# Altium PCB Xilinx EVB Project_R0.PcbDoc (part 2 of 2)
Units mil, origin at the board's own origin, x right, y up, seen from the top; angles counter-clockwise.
Board outline 8120 x 5778 mil, 6 copper layers (Top Layer, Mid-Layer 1, Mid-Layer 2, Mid-Layer 3, Mid-Layer 4, Bottom Layer); 283 components, 125 nets, 1037 pads, 1290 vias.
Unrouted connection lines stored in the file: 1.
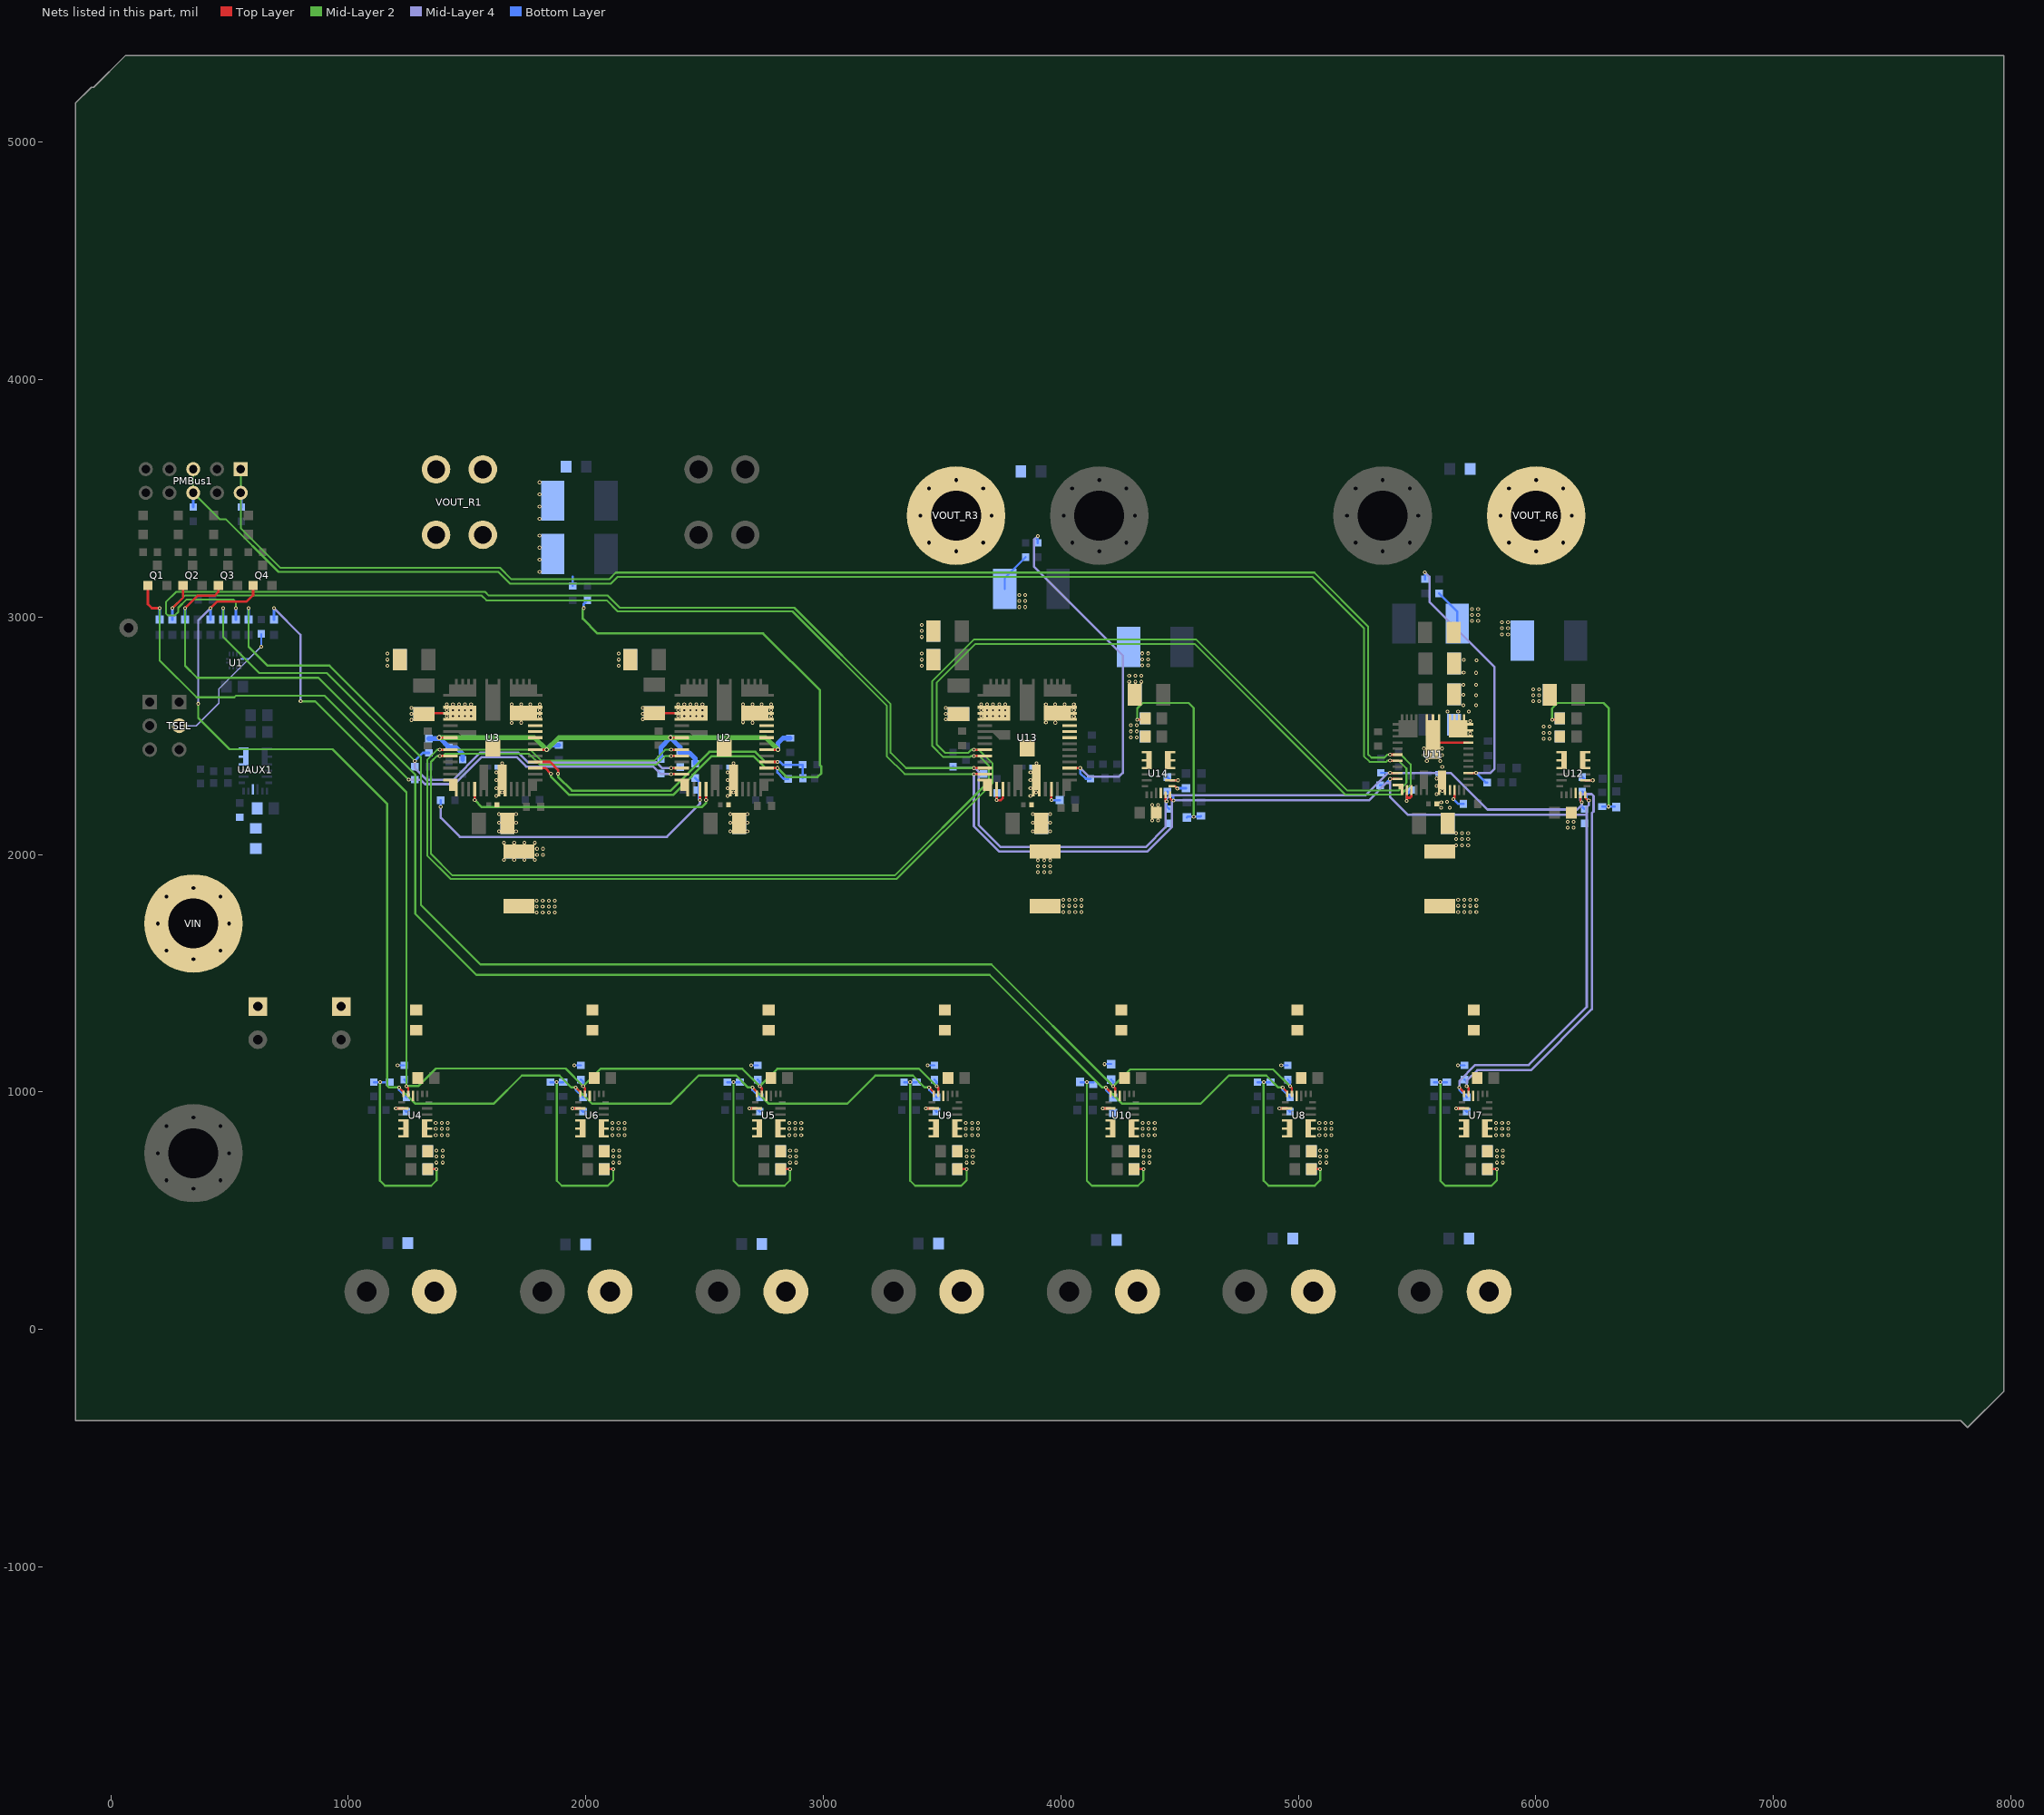
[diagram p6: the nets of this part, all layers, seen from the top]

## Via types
v1: diameter 15.75, hole 7.87, Top Layer to Bottom Layer, tented both sides, 1280 vias
v2: diameter 19.68, hole 11.81, Top Layer to Bottom Layer, tented both sides, 10 vias

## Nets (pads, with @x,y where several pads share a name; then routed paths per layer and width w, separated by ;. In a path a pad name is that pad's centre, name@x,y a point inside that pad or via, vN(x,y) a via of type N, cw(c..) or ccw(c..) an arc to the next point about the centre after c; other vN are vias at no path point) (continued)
NetR45_1: R45.1 U4.2 | length 82.7
  Top Layer w10: v1(1200.07,930.43) U4.2@1232.79,930.43
  Bottom Layer w10: v1(1200.07,930.43) 1231.07,930.43 R45.1@1244.5,917
NetR50_1: R50.1 U5.2 | length 82.7
  Top Layer w10: v1(2688.23,930.43) U5.2@2720.95,930.43
  Bottom Layer w10: v1(2688.23,930.43) 2719.23,930.43 R50.1@2732.67,917
NetR55_2: R55.2 U6.2 | length 82.7
  Top Layer w10: v1(1944.15,930.43) U6.2@1976.87,930.43
  Bottom Layer w10: v1(1944.15,930.43) 1975.15,930.43 R55.2@1988.58,917
NetR60_2: R60.2 U7.2 | length 82.7
  Top Layer w10: v1(5664.57,930.43) U7.2@5697.29,930.43
  Bottom Layer w10: v1(5664.57,930.43) 5695.57,930.43 R60.2@5709,917
NetR65_1: R65.1 U8.2 | length 82.7
  Top Layer w10: v1(4920.48,930.43) U8.2@4953.2,930.43
  Bottom Layer w10: v1(4920.48,930.43) 4951.48,930.43 R65.1@4964.92,917
NetR70_1: R70.1 U9.2 | length 82.7
  Top Layer w10: v1(3432.32,930.43) U9.2@3465.04,930.43
  Bottom Layer w10: v1(3432.32,930.43) 3463.32,930.43 R70.1@3476.75,917
NetR75_2: R75.2 U10.2 | length 82.7
  Top Layer w10: v1(4176.4,930.43) U10.2@4209.12,930.43
  Bottom Layer w10: v1(4176.4,930.43) 4207.4,930.43 R75.2@4220.83,917
NetR84_1: R84.1 R85.2 U11.3 | length 1159.2
  Top Layer w10: U11.3@5715.62,2343.63 v1(5747.6,2343.63)
  Mid-Layer 4 w10: v1(5533,3188) 5552,3169 5552,3063.06 5826,2789.06 5826,2361 5808.63,2343.63 v1(5747.6,2343.63)
  Bottom Layer w10: R85.2@5533,3159 v1(5533,3188) ; v1(5747.6,2343.63) 5788.23,2303 R84.1@5795,2303
NetR86_2: R86.2 U11.43 | length 90.9
  Top Layer w10: v1(5653,2233) 5657.55,2237.55 U11.43@5657.55,2271.78
  Bottom Layer w10: v1(5653,2233) 5673,2213 R86.2@5695,2213
NetR89_2: R89.2 U12.2 | length 82.7
  Top Layer w10: U12.2@6207.21,2312.4 v1(6239.93,2312.4)
  Bottom Layer w10: R89.2@6195.5,2325.83 6208.93,2312.4 v1(6239.93,2312.4)
NetR98_2: R98.2 R99.2 U13.3 | length 1509.4
  Top Layer w10: U13.3@4036.15,2364.05 v1(4081.82,2364.05)
  Mid-Layer 4 w10: v1(3903,3341) 3887,3325 3887,3212 4261,2838 4261,2344 4244,2327 4118.87,2327 v1(4081.82,2364.05)
  Bottom Layer w10: R99.2@3903,3312 v1(3903,3341) ; v1(4081.82,2364.05) 4081.82,2342.18 4105,2319 R98.2@4125,2319
NetR100_1: R100.1 U13.48 | length 80.1
  Top Layer w10: v1(3960.36,2228.81) U13.48@3960.36,2274.48
  Bottom Layer w10: v1(3960.36,2228.81) R100.1@3994.81,2228.81
NetR103_2: R103.2 U14.2 | length 82.7
  Top Layer w10: U14.2@4460.21,2312.4 v1(4492.93,2312.4)
  Bottom Layer w10: R103.2@4448.5,2325.83 4461.93,2312.4 v1(4492.93,2312.4)
NetR104_2: R104.2 U14.1 | length 63.1
  Top Layer w9: U14.1@4468.09,2286.81 4481.52,2286.81 v1(4490.5,2277.83)
  Bottom Layer w10: v1(4490.5,2277.83) 4491.67,2279 R104.2@4527,2279
NetU2_8: U2.8 U2.9 U2.10 U2.11 U2.12 U2.13 U2.51
  other v1: 2702,2555 2662,2557 2780,2581 2780,2607 2662,2633 2701.33,2633 2740.67,2633 2780,2633
NetU2_38: U2.38 U2.39
NetU2_42: U2.42 U3.42 | length 1097.4
  Top Layer w10: v1(1532.23,2228.81) U3.42@1532.23,2274.48 ; v1(2506.23,2228.81) U2.42@2506.23,2274.48
  Mid-Layer 2 w10: v1(1532.23,2228.81) 1562.04,2199 2489,2199 2506.23,2216.23 v1(2506.23,2228.81)
NetU3_8: U3.8 U3.9 U3.10 U3.11 U3.12 U3.13 U3.51
  other v1: 1688,2554 1728,2555 1806,2581 1806,2607 1688,2633 1727.33,2633 1766.67,2633 1806,2633
NetU3_38: U3.38 U3.39
NetU4_4: U4.4 U4.5 U4.6
NetU5_4: U5.4 U5.5 U5.6
NetU6_4: U6.4 U6.5 U6.6
NetU7_4: U7.4 U7.5 U7.6
NetU8_4: U8.4 U8.5 U8.6
NetU9_4: U9.4 U9.5 U9.6
NetU10_4: U10.4 U10.5 U10.6
NetU11_8: U11.8 U11.16 U11.17 U11.18 | length 153.5
  Top Layer w10: U11.16@5567,2483.39 5578.81,2471.58 U11.8@5715.62,2471.58
  other v1: 5541,2394 5597,2394 5529,2418 5605,2418 5529,2446 5605,2446
NetU11_33: U11.33 U11.34 U11.42
NetU12_4: U12.4 U12.5 U12.6
NetU13_8: U13.8 U13.9 U13.10 U13.11 U13.12 U13.13 U13.51
  other v1: 3977,2555 3937,2556 4055,2581 4055,2607 3937,2633 3976.33,2633 4015.67,2633 4055,2633
NetU13_38: U13.38 U13.39
NetU14_4: U14.4 U14.5 U14.6
NetUAUX1_4: UAUX1.4 UAUX1.5 UAUX1.6
SCL: PMBus1.1 PMBus1.2 R32.2 U2.33 U3.33 U11.28 U13.33 | length 13292.5
  Top Layer w10: v1(1385.18,2440.82) U3.33@1430.85,2440.82 ; v1(2359.18,2440.82) U2.33@2404.85,2440.82 ; v1(3634.18,2440.82) U13.33@3679.85,2440.82 ; v1(5386.4,2420.4) U11.28@5418.38,2420.4
  Mid-Layer 2 w8: PMBus1.1@547,3623 PMBus1.2@547,3523 547,3374.37 713.43,3207.94 1638.43,3207.94 1687.43,3158.94 2098.57,3158.94 2126.57,3186.94 5067.43,3186.94 5294,2960.37 5294,2421.37 5307.43,2407.94 5362.58,2407.94 5375.04,2420.4 v1(5386.4,2420.4) 5431.6,2420.4 5472.94,2379.06 5472.94,2293.94 5431.06,2252.06 5197.94,2252.06 4563,2887 3641,2887 3477,2723 3477,2464 3513.06,2427.94 3609.94,2427.94 3622.82,2440.82 v1(3634.18,2440.82) 3655.18,2440.82 3713,2383 3713,2301 3309,1897 1430.75,1897 1332,1995.75 1332,2399 1373.82,2440.82 v1(1385.18,2440.82) 1766.81,2440.82 1812.73,2394.9 2287.9,2394.9 2333.82,2440.82 2337.19,2440.82 2337.87,2441.5 2351.13,2441.5 2351.81,2440.82 v1(2359.18,2440.82)
  Bottom Layer w8: PMBus1.2@547,3523 PMBus1.2@550,3520
  Bottom Layer w10: R32.2@550,3463 PMBus1.2@550,3520
SDA: PMBus1.5 PMBus1.6 R33.1 U2.34 U3.34 U11.29 U13.34 | length 13278.9
  Top Layer w10: v1(1385.18,2415.23) U3.34@1430.85,2415.23 ; v1(2359.18,2415.23) U2.34@2404.85,2415.23 ; v1(3634.18,2415.23) U13.34@3679.85,2415.23 ; v1(5386.4,2394.81) U11.29@5418.38,2394.81
  Mid-Layer 2 w8: PMBus1.5@347,3623 PMBus1.6@347,3523 458,3412 484,3412 706,3190 1631,3190 1680,3141 2106,3141 2134,3169 5060,3169 5276.06,2952.94 5276.06,2413.94 5300,2390 5370.01,2390 5374.82,2394.81 v1(5386.4,2394.81) 5422.19,2394.81 5455,2362 5455,2301.37 5423.63,2270 5205.37,2270 4570.43,2904.94 3633.57,2904.94 3459.06,2730.43 3459.06,2456.57 3505.63,2410 3617.37,2410 3622.6,2415.23 v1(3634.18,2415.23) 3655.77,2415.23 3697,2374 3697,2307.63 3302.37,1913 1437.37,1913 1348,2002.37 1348,2389.63 1373.6,2415.23 v1(1385.18,2415.23) 1398.41,2415.23 1408,2424.82 1760.18,2424.82 1806.1,2378.9 2297.9,2378.9 2334.23,2415.23 v1(2359.18,2415.23)
  Bottom Layer w10: R33.1@347,3463 PMBus1.6@347,3523
SEQ_EN1: R17.2 R29.2 R36.2 R39.1 U2.36 | length 2577.4
  Top Layer w10: v1(2359.18,2364.05) U2.36@2404.85,2364.05
  Mid-Layer 2 w8: v1(473.22,3037) 473.22,2915.78 625,2764 910,2764 v1(1280,2394)
  Mid-Layer 4 w10: v1(1280,2394) 1280,2365 1331,2314 1440.54,2314 1554.54,2428 1716.46,2428 1756.46,2388 2297,2388 2320.95,2364.05 v1(2359.18,2364.05)
  Bottom Layer w10: R17.2@473.22,2989 v1(473.22,3037) ; R39.1@1280,2370 v1(1280,2394) 1314,2428 R36.2@1339,2428 ; v1(2359.18,2364.05) 2393.05,2364.05 R29.2@2397,2368
SEQ_EN2: R16.2 R57.1 R81.1 R87.1 R95.1 R101.1 U7.17 U11.31 U12.17 U13.36 U14.17 | length 9496.6
  Top Layer w9: U14.17@4440.53,2251.37 4440.53,2227.47 v1(4445,2223) ; v1(5709,1024) 5716.97,1016.03 U7.17@5716.97,991.46 ; U12.17@6187.53,2251.37 6187.53,2225.47 v1(6193,2220)
  Top Layer w10: v1(3634.18,2364.05) U13.36@3679.85,2364.05 ; v1(5386.4,2343.63) U11.31@5418.38,2343.63
  Mid-Layer 2 w8: v1(526.67,3037) 526.67,3062.33 515,3074 319.07,3074 284,3038.93 284,3021 270,3007 240,3007 232,3015 232,3063 275,3106 1576,3106 1592,3090 2093,3090 2144,3039 2877.63,3039 3283,2633.63 3283,2429 3347.95,2364.05 v1(3634.18,2364.05)
  Mid-Layer 4 w10: v1(3634.18,2364.05) 3638.11,2364.05 3655.06,2347.1 3655.06,2328.76 3654,2327.7 3654,2124.46 3747.46,2031 4357.54,2031 4440.53,2113.98 4440.53,2218.53 v1(4445,2223) 4445,2234.85 4458.85,2248.7 5282.7,2248.7 5377.63,2343.63 v1(5386.4,2343.63) 5641.37,2343.63 5796,2189 6174,2189 6195,2210 6195,2220.36 6187.53,2227.83 6187.53,2244.53 6197,2254 6235,2254 6243,2246 6243,2181 6236,2174 6236,1348.59 5978.91,1091.5 5753.91,1091.5 5709,1046.59 v1(5709,1024)
  Bottom Layer w9: v1(4445,2223) 4445,2203.33 R101.1@4457.5,2190.83 ; R81.1@5347,2344 5386.03,2344 v1(5386.4,2343.63) ; R57.1@5700,1052 5709,1043 v1(5709,1024) ; v1(6193,2220) 6193,2202.33 R87.1@6204.5,2190.83
  Bottom Layer w10: R16.2@526.67,2989 v1(526.67,3037) ; R95.1@3546,2370 3551.95,2364.05 v1(3634.18,2364.05)
SEQ_EN3: R15.2 R62.2 R73.1 U8.17 U10.17 | length 5920.5
  Top Layer w9: v1(4220.83,1024) 4228.81,1016.03 U10.17@4228.81,991.46 ; v1(4964.92,1024) 4972.89,1016.03 U8.17@4972.89,991.46
  Mid-Layer 2 w9: v1(580.11,3037) 580.11,2874.89 660,2795 921,2795 1306,2410 1306,1787 1556,1537 3707.83,1537 v1(4220.83,1024) 4291.83,1095 4893.92,1095 v1(4964.92,1024)
  Bottom Layer w9: R73.1@4211.83,1052 4220.83,1043 v1(4220.83,1024) ; R62.2@4955.92,1052 4964.92,1043 v1(4964.92,1024)
  Bottom Layer w10: R15.2@580.11,2989 v1(580.11,3037)
SEQ_EN4: R9.2 R42.2 R47.2 R52.1 R67.2 U4.17 U5.17 U6.17 U9.17 | length 5014.7
  Top Layer w9: v1(1244.5,1024) 1252.47,1016.03 U4.17@1252.47,991.46 ; v1(1988.58,1024) 1996.56,1016.03 U6.17@1996.56,991.46 ; v1(2732.67,1024) 2740.64,1016.03 U5.17@2740.64,991.46 ; v1(3476.75,1024) 3484.72,1016.03 U9.17@3484.72,991.46
  Mid-Layer 2 w9: v1(799,2645) 861,2645 1244.5,2261.5 v1(1244.5,1024) ; v1@1244.92,1024.42 1294.42,1024.42 1368.42,1098.42 1915,1098.42 v1@1989,1024.42 ; v1(1988.58,1024) v1@1989,1024.42 ; v1(3476.75,1024) 3402.75,1098 2806.67,1098 v1(2732.67,1024) 2658.67,1098 2062.58,1098 v1@1989,1024.42
  Mid-Layer 4 w9: v1(687,3037) 799,2925 v1(799,2645)
  Bottom Layer w9: R42.2@1235.5,1052 1244.5,1043 v1(1244.5,1024) ; R52.1@1979.58,1052 1988.58,1043 v1(1988.58,1024) ; R47.2@2723.67,1052 2732.67,1043 v1(2732.67,1024) ; R67.2@3467.75,1052 3476.75,1043 v1(3476.75,1024)
  Bottom Layer w10: R9.2@687,2989 v1(687,3037)
SEQ_PG1: Q1.1 R10.1 R31.2 R38.1 U2.37 | length 2970.8
  Top Layer w10: Q1.1@156,3133 156,3054 173,3037 v1(206,3037) ; v1(2359.18,2338.46) U2.37@2404.85,2338.46
  Mid-Layer 2 w8: v1(206,3037) 206,2817 361,2662 520,2662 526,2668 901,2668 v1(1254,2315)
  Mid-Layer 4 w10: v1(1254,2315) 1304.54,2315 1323.54,2296 1448,2296 1562,2410 1709,2410 1749,2370 2284,2370 2315.54,2338.46 v1(2359.18,2338.46)
  Bottom Layer w10: R10.1@206,2989 v1(206,3037) ; v1(1254,2315) R38.1@1280,2315 ; R31.2@2316,2341 2318.54,2338.46 v1(2359.18,2338.46)
SEQ_PG2: Q2.1 R11.1 R60.1 R83.1 R89.1 R97.2 R103.1 U7.18 U11.32 U12.18 U13.37 U14.18 | length 9111.9
  Top Layer w9: v1(259.44,3037) 304,3081.56 Q2.1@304,3133 ; U14.18@4460.21,2251.37 4460.9,2250.69 4460.9,2234.43 v1@4467.5,2227.83 ; v1(5678,1019) 5697.29,999.71 U7.18@5697.29,991.46 ; U12.18@6207.21,2251.37 6207.21,2239.79 6220,2227 v1(6223,2227)
  Top Layer w10: v1(3634.18,2338.46) U13.37@3679.85,2338.46 ; v1(5386.4,2318.04) U11.32@5418.38,2318.04
  Mid-Layer 2 w8: v1(259.44,3037) 312.44,3090 1562,3090 1582,3070 2088,3070 2134,3024 2870,3024 3267,2627 3267,2414 3342.54,2338.46 v1(3634.18,2338.46)
  Mid-Layer 4 w10: v1(3634.18,2338.46) 3634.18,2118.82 3740,2013 4365,2013 4467.5,2115.5 4467.5,2221.33 v1(4474,2227.83) 5296.83,2227.83 5370,2301 5385,2301 ; v1(5386.4,2318.04) 5386.4,2242.6 5462,2167 6214.5,2167 ; v1(5678,1019) 5678,1046 5745,1113 5970,1113 6214.5,1357.5 6214.5,2167 ; v1(6223,2227) 6223,2209 6214.5,2200.5 6214.5,2167
  Bottom Layer w9: R103.1@4448.5,2265.83 4474,2240.33 v1(4474,2227.83) ; v1(5678,1019) 5678,1008 R60.1@5709,977 ; R89.1@6195.5,2265.83 6214.5,2246.83 6214.5,2235.5 v1(6223,2227)
  Bottom Layer w10: R11.1@259.44,2989 v1(259.44,3037) ; v1(3634.18,2338.46) 3674.46,2338.46 R97.2@3675,2339 ; R83.1@5344,2291 5359.36,2291 v1(5386.4,2318.04)
SEQ_PG3: Q3.1 R12.1 R65.2 R75.1 U8.18 U10.18 | length 6465.1
  Top Layer w9: v1(4189.83,1019) 4209.12,999.71 U10.18@4209.12,991.46 ; v1(4933.92,1019) 4953.2,999.71 U8.18@4953.2,991.46
  Top Layer w10: v1(312.89,3037) 364.89,3089 437,3089 453,3105 Q3.1@453,3132
  Mid-Layer 2 w9: v1(312.89,3037) 312.89,2794.11 363,2744 874,2744 1282,2336 1282,1750 1539,1493 3700,1493 4174,1019 v1(4189.83,1019) 4258.83,950 4588.33,950 4707.33,1069 4865.17,1069 4915.17,1019 v1(4933.92,1019)
  Bottom Layer w9: v1(4189.83,1019) 4189.83,1008 R75.1@4220.83,977 ; v1(4933.92,1019) 4933.92,1008 R65.2@4964.92,977
  Bottom Layer w10: R12.1@312.89,2989 v1(312.89,3037)
SEQ_PG4: Q4.1 R13.1 R45.2 R50.2 R55.1 R70.2 U4.18 U5.18 U6.18 U9.18 | length 5845.7
  Top Layer w9: v1(1213.5,1019) 1232.79,999.71 U4.18@1232.79,991.46 ; v1(1957.58,1019) 1976.87,999.71 U6.18@1976.87,991.46 ; v1(2701.67,1019) 2720.95,999.71 U5.18@2720.95,991.46 ; v1(3445.75,1019) 3465.04,999.71 U9.18@3465.04,991.46
  Top Layer w10: v1(419.78,3037) 447.78,3065 572,3065 599,3092 Q4.1@599,3130
  Mid-Layer 2 w9: v1(368,2635) 368,2575 500,2443 934,2443 1163,2214 1163,1028 1172,1019 v1(1213.5,1019) 1282.5,950 1612,950 1731,1069 1888.83,1069 1938.83,1019 v1(1957.58,1019) 2026.58,950 2356.08,950 2475.08,1069 2632.92,1069 2682.92,1019 v1(2701.67,1019) 2770.67,950 3100.17,950 3219.17,1069 3377,1069 3427,1019 v1(3445.75,1019)
  Mid-Layer 4 w9: v1(368,2635) 368,2985.22 v1(419.78,3037)
  Bottom Layer w9: v1(1213.5,1019) 1213.5,1008 R45.2@1244.5,977 ; v1(1957.58,1019) 1957.58,1008 R55.1@1988.58,977 ; v1(2701.67,1019) 2701.67,1008 R50.2@2732.67,977 ; v1(3445.75,1019) 3445.75,1008 R70.2@3476.75,977
  Bottom Layer w10: R13.1@419.78,2989 v1(419.78,3037)
TAKE1: R22.1 R35.1 R41.2 U2.41 | length 1418.6
  Top Layer w10: v1(2480.64,2228.81) U2.41@2480.64,2274.48
  Mid-Layer 4 w10: v1(1389,2200) 1389,2155 1470,2074 2341,2074 2480.64,2213.64 v1(2480.64,2228.81)
  Bottom Layer w10: v1(1389,2200) R41.2@1389,2228 ; R22.1@2460,2322 2475.92,2306.08 2475.92,2233.53 v1(2480.64,2228.81)
TAKE2: R91.1 U13.40 U13.41 | length 142.3
  Top Layer w10: U13.40@3730.05,2274.48 v1(3730.05,2228.81) 3746.81,2228.81 3755.64,2237.64 U13.41@3755.64,2274.48
  Bottom Layer w10: v1(3730.05,2228.81) 3730.05,2258.05 R91.1@3731,2259
TAKE3: R77.2 U11.35 U11.36 | length 148.8
  Top Layer w10: v1(5456.76,2225.76) 5456.76,2242.24 ; U11.35@5456.76,2271.78 5456.76,2242.24 ; U11.36@5476.45,2271.78 5476.45,2245.45 5470,2239 5460,2239 5456.76,2242.24
  Bottom Layer w10: v1(5456.76,2225.76) 5456.76,2252.76 R77.2@5475,2271
TSEL: R5.1 TSEL.2 U1.11 | length 673.8
  Mid-Layer 4 w6: TSEL.2@288,2542 360,2542 455,2637 455,2697 v1(633.56,2875.56)
  Bottom Layer w6: U1.11@553.51,2823.87 581.87,2823.87 v1(633.56,2875.56) R5.1@633.56,2929
VCC_U1: C18.2 C29.2 R22.2 R29.1 R30.1 R31.1 R36.1 R37.1 U2.6 U2.31 U3.6 U3.31 | length 2310.1
  Top Layer w10: v2(1383,2492) U3.31@1430.85,2492 ; U3.6@1787.15,2440.82 v2(1835,2440.82) ; v2(2357,2492) U2.31@2404.85,2492 ; U2.6@2761.15,2440.82 v2(2809,2440.82)
  Mid-Layer 2 w20: v2(1383,2492) 1783.82,2492 v2(1835,2440.82) 1886.18,2492 v2(2357,2492) 2757.82,2492 v2(2809,2440.82)
  Bottom Layer w20: R36.1@1339,2488 1379,2488 v2(1383,2492) R30.1@1424,2451 1454,2451 1482,2423 R37.1@1482,2399 ; v2(1835,2440.82) 1854.18,2460 C29.2@1886,2460 ; R31.1@2316,2401 2316,2451 v2(2357,2492) 2397,2452 R29.1@2397,2428 2437,2428 2460,2405 R22.2@2460,2382 ; v2(2809,2440.82) 2809,2469 2830,2490 C18.2@2861,2490
VIN: C12.1 C13.1 R1.1 R23.1 R24.1 R43.1 R48.1 R53.1 R58.1 R63.1 R68.1 R72.1 R78.1 R92.1 VIN.1 VIN.2 VIN.3 VIN.4 VIN.5 VIN.6 VIN.7 VIN.8 VIN.9
  other v1: 1793,1755 1818.5,1755 1844,1755 1869.5,1755 4010,1758 4035.5,1758 4061,1758 4086.5,1758 5673,1758 5698.5,1758 5724,1758 5749.5,1758 1793,1780.5 1818.5,1780.5 1844,1780.5 1869.5,1780.5 4010,1783.5 4035.5,1783.5 4061,1783.5 4086.5,1783.5 5673,1783.5 5698.5,1783.5 5724,1783.5 5749.5,1783.5 1793,1806 1818.5,1806 1844,1806 1869.5,1806 4010,1809 4035.5,1809 4061,1809 4086.5,1809 5673,1809 5698.5,1809 5724,1809 5749.5,1809
VIN1: C14.2 C15.2 C16.2 C17.2 C25.2 C26.2 C27.2 C28.2 R23.2 R24.2 U2.45 U2.46 U3.45 U3.46
  other v1: 1655,1977 1698.33,1977 1741.67,1977 1785,1977 1794,1998.5 1819.5,1998.5 1794,2024 1819.5,2024 1655,2049 1698.33,2049 1741.67,2049 1785,2049 1634,2097 1706,2097 2608,2097 2680,2097 1634,2133.5 1706,2133.5 2608,2133.5 2680,2133.5 1634,2170 1706,2170 2608,2170 2680,2170 1623,2246 2597,2246 1647,2262 2621,2262 1623,2279.33 2597,2279.33 1623,2312.67 2597,2312.67 1623,2346 2597,2346 1648,2384 2622,2384
VIN2: C68.2 R72.2 R73.2 U10.16 | length 28
  Bottom Layer w8: v1(4183.83,1117) R73.2@4211.83,1117
VIN3: C102.2 C103.2 C104.2 C105.2 C114.2 R92.2 R101.2 U13.45 U13.46 U14.16
  other v1: 3904,1925 3929.5,1925 3955,1925 3904,1950.5 3929.5,1950.5 3955,1950.5 3904,1976 3929.5,1976 3955,1976 3883,2097 3955,2097 3883,2133.5 3955,2133.5 4385,2144 4409,2144 3883,2170 3955,2170 4385,2209 4409,2209 3872,2246 3896,2262 3872,2279.33 3872,2312.67 3872,2346 3897,2384
VIN4: C44.2 R52.2 R53.2 U6.16 | length 28
  Bottom Layer w8: v1(1951.58,1112) R52.2@1979.58,1112
VIN5: C50.2 R57.2 R58.2 U7.16 | length 28
  Bottom Layer w8: v1(5672,1112) R57.2@5700,1112
VIN6: C76.2 C77.2 C90.2 C120.2 C121.2 R78.2 R87.2 U11.40 U11.41 U12.16
  other v1: 5664,2039 5689.5,2039 5715,2039 5664,2064.5 5689.5,2064.5 5715,2064.5 5664,2090 5689.5,2090 5715,2090 6134,2112.5 6159.5,2112.5 6134,2138 6159.5,2138 5601,2197 5637,2197 5602,2220 5626,2221 5582,2254 5606,2267 5582,2289 5582,2320 5606,2369
VIN7: C56.2 R62.1 R63.2 U8.16 | length 28
  Bottom Layer w8: v1(4927.92,1112) R62.1@4955.92,1112
VIN8: C32.2 R42.1 R43.2 U4.16 | length 28
  Bottom Layer w8: v1(1207.5,1112) R42.1@1235.5,1112
VIN9: C38.2 R47.1 R48.2 U5.16 | length 28
  Bottom Layer w8: v1(2696,1112) R47.1@2724,1112
VIN10: C62.2 R67.1 R68.2 U9.16 | length 28
  Bottom Layer w8: v1(3439.75,1112) R67.1@3467.75,1112
VINAUX: C1.2 R1.2 R2.1 UAUX1.16
VOS+: C11.1 R25.2 R27.2 U2.4 U3.4 | length 1384.4
  Top Layer w10: U3.4@1787.15,2389.64 1849.36,2389.64 1883,2356 v1(1883,2340) ; U2.4@2761.15,2389.64 v1(2806.82,2389.64)
  Mid-Layer 2 w10: v1(1883,2340) 1883,2327 1941,2269 2357.81,2269 2520.81,2432 2713.46,2432 2755.82,2389.64 v1(2806.82,2389.64)
  Bottom Layer w10: v1(2806.82,2389.64) 2818.36,2389.64 2830,2378 R27.2@2852,2378 R25.2@2913,2378 C11.1@2913,2322
VOS-: R27.1 R28.1 U2.3 U3.3 | length 3052.5
  Top Layer w10: U3.3@1787.15,2364.05 1828.95,2364.05 v1(1853,2340) ; U2.3@2761.15,2364.05 v1(2806.82,2364.05)
  Mid-Layer 2 w10: v1(1853,2340) 1853,2328 1930,2251 2367,2251 2530,2414 2706,2414 2755.95,2364.05 v1(2806.82,2364.05) 2844.87,2326 2976,2326 2992,2342 2992,2370 2985,2377 2985,2692.7 2746.7,2931 2049,2931 1987,2993 1987,3034 v1(1991,3038)
  Bottom Layer w10: v1(1991,3038) 1991,3055 R28.1@2007,3071 ; v1(2806.82,2364.05) 2806.82,2345.18 2834,2318 R27.1@2852,2318
VOUT_R1: C5.1 C6.1 C7.2 C8.2 C9.2 C10.2 C21.2 C22.2 C23.2 C24.2 R26.2 RL1.1 U2.26 U2.27 U2.28 U3.26 U3.27 U3.28 VOUT_R1.1 VOUT_R1.2 VOUT_R1.3 VOUT_R1.4 | length 369.8
  Top Layer w10: C21.2@1315.64,2594.36 U3.27@1430.85,2594.36 U3.28@1481.05,2594.36 ; C7.2@2289.64,2594.36 U2.27@2404.85,2594.36 U2.28@2455.05,2594.36
  Bottom Layer w10: R26.2@1945,3131 1945,3170
  other v1: 1266,2566.5 2240,2570 1415,2582 1440.5,2582 1466,2582 1491.5,2582 1517,2582 2389,2582 2414.5,2582 2440,2582 2465.5,2582 2491,2582 1266,2592 2240,2592 1415,2607.5 1440.5,2607.5 1466,2607.5 1491.5,2607.5 1517,2607.5 2389,2607.5 2414.5,2607.5 2440,2607.5 2465.5,2607.5 2491,2607.5 1266,2617.5 2240,2617.5 1415,2633 1440.5,2633 1466,2633 1491.5,2633 1517,2633 2389,2633 2414.5,2633 2440,2633 2465.5,2633 2491,2633 1165,2795.14 2139,2795.14 1165,2820.64 2139,2820.64 1165,2846.14 2139,2846.14 1805.36,3190.14 1805.36,3241.14 1805.36,3292.14 1805.36,3343.14 1805.36,3414.14 1805.36,3465.14 1805.36,3516.14 1805.36,3567.14
VOUT_R2: C69.2 C70.2 C71.2 C72.2 C73.2 R74.2 RL2.1 U10.7 U10.8 U10.9 VOUT_R2.1 | length 811.2
  Top Layer w9: C70.2@4307.83,675 v1(4347.83,675)
  Mid-Layer 2 w9: v1(4109.83,1041) 4109.83,626 4130.83,605 4324.83,605 4347.83,628 v1(4347.83,675)
  Bottom Layer w9: R74.2@4083.83,1041 v1(4109.83,1041) C73.2@4136.83,1041
  other v1: 4347.83,675 4347.83,702.5 4373.33,702.5 4347.83,728 4373.33,728 4347.83,753.5 4373.33,753.5 4344.33,818.5 4369.83,818.5 4395.33,818.5 4344.33,844 4369.83,844 4395.33,844 4344.33,869.5 4369.83,869.5 4395.33,869.5
VOUT_R3: C96.1 C97.1 C98.2 C99.2 C100.2 C101.2 C108.2 C109.2 C110.2 C111.2 C115.2 C116.2 C117.2 C118.2 C119.2 R94.1 R102.2 RL3.1 U13.26 U13.27 U13.28 U14.7 U14.8 U14.9 VOUT_R3.1 VOUT_R3.2 VOUT_R3.3 VOUT_R3.4 VOUT_R3.5 VOUT_R3.6 VOUT_R3.7 VOUT_R3.8 VOUT_R3.9 | length 1033
  Top Layer w9: v1(4321.5,2567.83) C116.2@4361.5,2567.83
  Mid-Layer 2 w9: v1(4321.5,2567.83) 4321.5,2614.83 4344.5,2637.83 4538.5,2637.83 4559.5,2616.83 v1(4559.5,2159)
  Bottom Layer w9: C97.1@3764,3118 3764,3164 R94.1@3852,3252 ; R102.2@4531,2156 4534,2159 v1(4559.5,2159) 4587,2159 C119.2@4590,2162
  other v1: 4294.5,2493 4320,2493 4294.5,2518.5 4320,2518.5 4294.5,2544 4320,2544 3515,2569 3664,2582 3689.5,2582 3715,2582 3740.5,2582 3766,2582 3515,2592 3664,2607.5 3689.5,2607.5 3715,2607.5 3740.5,2607.5 3766,2607.5 3515,2617.5 3664,2633 3689.5,2633 3715,2633 3740.5,2633 3766,2633 4288,2727 4313.5,2727 4339,2727 4288,2752.5 4313.5,2752.5 4339,2752.5 3414,2795.14 4342,2796 4367.5,2796 3414,2820.64 4342,2821.5 4367.5,2821.5 3414,2846.14 4342,2847 4367.5,2847 3414,2916.14 3414,2941.64 3414,2967.14 3825,3042 3850.5,3042 3825,3067.5 3850.5,3067.5 3825,3093 3850.5,3093
VOUT_R4: C45.2 C46.2 C47.2 C48.2 C49.2 R54.2 RL4.1 U6.7 U6.8 U6.9 VOUT_R4.1 | length 811.2
  Top Layer w9: C46.2@2075.58,675 v1(2115.58,675)
  Mid-Layer 2 w9: v1(1877.58,1041) 1877.58,626 1898.58,605 2092.58,605 2115.58,628 v1(2115.58,675)
  Bottom Layer w9: R54.2@1851.58,1041 v1(1877.58,1041) C49.2@1904.58,1041
  other v1: 2115.58,675 2115.58,702.5 2141.08,702.5 2115.58,728 2141.08,728 2115.58,753.5 2141.08,753.5 2112.08,818.5 2137.58,818.5 2163.08,818.5 2112.08,844 2137.58,844 2163.08,844 2112.08,869.5 2137.58,869.5 2163.08,869.5
VOUT_R5: C51.2 C52.2 C53.2 C54.2 C55.2 R59.2 RL5.1 U7.7 U7.8 U7.9 VOUT_R5.1 | length 811.2
  Top Layer w9: C52.2@5796,675 v1(5836,675)
  Mid-Layer 2 w9: v1(5598,1041) 5598,626 5619,605 5813,605 5836,628 v1(5836,675)
  Bottom Layer w9: R59.2@5572,1041 v1(5598,1041) C55.2@5625,1041
  other v1: 5836,702.5 5861.5,702.5 5836,728 5861.5,728 5836,753.5 5861.5,753.5 5832.5,818.5 5858,818.5 5883.5,818.5 5832.5,844 5858,844 5883.5,844 5832.5,869.5 5858,869.5 5883.5,869.5
VOUT_R6: C74.1 C75.1 C79.2 C80.2 C81.2 C82.2 C84.2 C85.2 C86.2 C87.2 C91.2 C92.2 C93.2 C94.2 C95.2 R80.1 R88.2 RL6.1 U11.9 U11.10 U11.11 U11.12 U11.13 U11.14 U11.15 U12.7 U12.8 U12.9 VOUT_R6.1 VOUT_R6.2 VOUT_R6.3 VOUT_R6.4 VOUT_R6.5 VOUT_R6.6 VOUT_R6.7 VOUT_R6.8 VOUT_R6.9 | length 969.7
  Top Layer w9: v1(6068.5,2567.83) C93.2@6108.5,2567.83
  Mid-Layer 2 w9: v1(6068.5,2567.83) 6068.5,2614.83 6091.5,2637.83 6285.5,2637.83 6306.5,2616.83 v1(6306.5,2201.83)
  Bottom Layer w9: C95.2@6279.5,2201.83 v1(6306.5,2201.83) R88.2@6332.5,2201.83
  Bottom Layer w10: R80.1@5593,3099 5669,3023 C75.1@5669,2972
  other v1: 6032.5,2487 6058,2487 5723,2509 6032.5,2512.5 6058,2512.5 6032.5,2538 6058,2538 5723,2562 5628,2602 5673,2602 5718,2602 5748,2628 5695,2629 5988.5,2645 6014,2645 5748,2671 5988.5,2670.5 6014,2670.5 5695,2672 5988.5,2696 6014,2696 5748,2714 5695,2715 5749,2765 5696,2766 5750,2818 5697,2819 5857.5,2927 5883,2927 5857.5,2952.5 5883,2952.5 5857.5,2978 5883,2978 5731.5,2983 5757,2983 5731.5,3008.5 5757,3008.5 5731.5,3034 5757,3034
VOUT_R7: C57.2 C58.2 C59.2 C60.2 C61.2 R64.1 RL7.1 U8.7 U8.8 U8.9 VOUT_R7.1 | length 811.2
  Top Layer w9: C58.2@5051.92,675 v1(5091.92,675)
  Mid-Layer 2 w9: v1(4853.92,1041) 4853.92,626 4874.92,605 5068.92,605 5091.92,628 v1(5091.92,675)
  Bottom Layer w9: R64.1@4827.92,1041 v1(4853.92,1041) C61.2@4880.92,1041
  other v1: 5091.92,675 5091.92,702.5 5117.42,702.5 5091.92,728 5117.42,728 5091.92,753.5 5117.42,753.5 5088.42,818.5 5113.92,818.5 5139.42,818.5 5088.42,844 5113.92,844 5139.42,844 5088.42,869.5 5113.92,869.5 5139.42,869.5
VOUT_R8: C33.2 C34.2 C35.2 C36.2 C37.2 R44.1 RL8.1 U4.7 U4.8 U4.9 VOUT_R8.1 | length 811.2
  Top Layer w9: C34.2@1331.5,675 v1(1371.5,675)
  Mid-Layer 2 w9: v1(1133.5,1041) 1133.5,626 1154.5,605 1348.5,605 1371.5,628 v1(1371.5,675)
  Bottom Layer w9: R44.1@1107.5,1041 v1(1133.5,1041) C37.2@1160.5,1041
  other v1: 1371.5,675 1371.5,702.5 1397,702.5 1371.5,728 1397,728 1371.5,753.5 1397,753.5 1368,818.5 1393.5,818.5 1419,818.5 1368,844 1393.5,844 1419,844 1368,869.5 1393.5,869.5 1419,869.5
VOUT_R9: C39.2 C40.2 C41.2 C42.2 C43.2 R49.1 RL9.1 U5.7 U5.8 U5.9 VOUT_R9.1 | length 811.2
  Top Layer w9: C40.2@2819.67,675 v1(2859.67,675)
  Mid-Layer 2 w9: v1(2621.67,1041) 2621.67,626 2642.67,605 2836.67,605 2859.67,628 v1(2859.67,675)
  Bottom Layer w9: R49.1@2595.67,1041 v1(2621.67,1041) C43.2@2648.67,1041
  other v1: 2859.67,675 2859.67,702.5 2885.17,702.5 2859.67,728 2885.17,728 2859.67,753.5 2885.17,753.5 2856.17,818.5 2881.67,818.5 2907.17,818.5 2856.17,844 2881.67,844 2907.17,844 2856.17,869.5 2881.67,869.5 2907.17,869.5
VOUT_R10: C63.2 C64.2 C65.2 C66.2 C67.2 R69.1 RL10.1 U9.7 U9.8 U9.9 VOUT_R10.1 | length 811.2
  Top Layer w9: C64.2@3563.75,675 v1(3603.75,675)
  Mid-Layer 2 w9: v1(3365.75,1041) 3365.75,626 3386.75,605 3580.75,605 3603.75,628 v1(3603.75,675)
  Bottom Layer w9: R69.1@3339.75,1041 v1(3365.75,1041) C67.2@3392.75,1041
  other v1: 3603.75,675 3603.75,702.5 3629.25,702.5 3603.75,728 3629.25,728 3603.75,753.5 3629.25,753.5 3600.25,818.5 3625.75,818.5 3651.25,818.5 3600.25,844 3625.75,844 3651.25,844 3600.25,869.5 3625.75,869.5 3651.25,869.5
pads on no net: EN.3 PMBus1.9 PMBus1.10 TSEL.3 U1.0 U2.2 U2.7 U2.29 U2.47 U3.2 U3.7 U3.29 U3.47 U4.10 U4.11 U4.15 U5.10 U5.11 U5.15 U6.10 U6.11 U6.15 U7.10 U7.11 U7.15 U8.10 U8.11 U8.15 U9.10 U9.11 U9.15 U10.10 U10.11 U10.15 U11.2 U11.7 U11.37 U12.10 U12.11 U12.15 U13.2 U13.7 U13.29 U13.42 U13.47 U14.10 U14.11 U14.15 UAUX1.2 UAUX1.10 UAUX1.11 UAUX1.15 UAUX1.18

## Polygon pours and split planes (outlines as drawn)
GND on Top Layer "Top Layer-No Net" (solid, remove dead copper, pour order 126): -71,3726 -71,75 78,-74 6661,-74 6820,85 6820,3745 6710,3855
VIN on Top Layer "Top Layer-No Net" (solid, remove dead copper, pour order 123): 550,1313 6066,1313 6101,1348 6101,1867 6079,1889 6073,1895 5945,1895 1506,1895 1411,1990 1263,2138 -25,2138 -25,1332 -6,1313
VIN8 on Top Layer "Top Layer-No Net" (solid, remove dead copper, pour order 95): 1266.5,961 1266.5,1029 1253.5,1042 1198.5,1097 1198.5,1120 1198.5,1288 1203.5,1293 1307.5,1293 1309.5,1291 1314.5,1286 1314.5,1081 1314.5,1027 1307.5,1020 1306.5,1019 1296.5,1019 1285.5,1019 1278.5,1012 1278.5,961
VOUT_R8 on Top Layer "Top Layer-No Net" (solid, remove dead copper, pour order 109): 1305.5,887 1305.5,501 1279.5,475 1219.5,415 1219.5,236 1219.5,-23 1228.5,-32 1524.5,-32 1529.5,-27 1529.5,876 1518.5,887
VIN4 on Top Layer "Top Layer-No Net" (solid, remove dead copper, pour order 96): 2010.58,961 2010.58,1029 1997.58,1042 1942.58,1097 1942.58,1120 1942.58,1288 1947.58,1293 2051.58,1293 2053.58,1291 2058.58,1286 2058.58,1081 2058.58,1027 2051.58,1020 2050.58,1019 2040.58,1019 2029.58,1019 2022.58,1012 2022.58,961
VOUT_R4 on Top Layer "Top Layer-No Net" (solid, remove dead copper, pour order 110): 2049.58,887 2049.58,501 2023.58,475 1963.58,415 1963.58,236 1963.58,-23 1972.58,-32 2268.58,-32 2273.58,-27 2273.58,876 2262.58,887
VIN9 on Top Layer "Top Layer-No Net" (solid, remove dead copper, pour order 97): 2754.67,961 2754.67,1029 2741.67,1042 2686.67,1097 2686.67,1120 2686.67,1288 2691.67,1293 2795.67,1293 2797.67,1291 2802.67,1286 2802.67,1081 2802.67,1027 2795.67,1020 2794.67,1019 2784.67,1019 2773.67,1019 2766.67,1012 2766.67,961
VOUT_R9 on Top Layer "Top Layer-No Net" (solid, remove dead copper, pour order 111): 2793.67,887 2793.67,501 2767.67,475 2707.67,415 2707.67,236 2707.67,-23 2716.67,-32 3012.67,-32 3017.67,-27 3017.67,876 3006.67,887
VIN10 on Top Layer "Top Layer-No Net" (solid, remove dead copper, pour order 98): 3498.75,961 3498.75,1029 3485.75,1042 3430.75,1097 3430.75,1120 3430.75,1288 3435.75,1293 3539.75,1293 3541.75,1291 3546.75,1286 3546.75,1081 3546.75,1027 3539.75,1020 3538.75,1019 3528.75,1019 3517.75,1019 3510.75,1012 3510.75,961
VOUT_R10 on Top Layer "Top Layer-No Net" (solid, remove dead copper, pour order 112): 3537.75,887 3537.75,501 3511.75,475 3451.75,415 3451.75,236 3451.75,-23 3460.75,-32 3756.75,-32 3761.75,-27 3761.75,876 3750.75,887
VIN2 on Top Layer "Top Layer-No Net" (solid, remove dead copper, pour order 99): 4242.83,961 4242.83,1029 4229.83,1042 4174.83,1097 4174.83,1120 4174.83,1288 4179.83,1293 4283.83,1293 4285.83,1291 4290.83,1286 4290.83,1081 4290.83,1027 4283.83,1020 4282.83,1019 4272.83,1019 4261.83,1019 4254.83,1012 4254.83,961
VOUT_R2 on Top Layer "Top Layer-No Net" (solid, remove dead copper, pour order 113): 4281.83,887 4281.83,501 4255.83,475 4195.83,415 4195.83,236 4195.83,-23 4204.83,-32 4500.83,-32 4505.83,-27 4505.83,876 4494.83,887
VIN7 on Top Layer "Top Layer-No Net" (solid, remove dead copper, pour order 100): 4986.92,961 4986.92,1029 4973.92,1042 4918.92,1097 4918.92,1120 4918.92,1288 4923.92,1293 5027.92,1293 5029.92,1291 5034.92,1286 5034.92,1081 5034.92,1027 5027.92,1020 5026.92,1019 5016.92,1019 5005.92,1019 4998.92,1012 4998.92,961
VOUT_R7 on Top Layer "Top Layer-No Net" (solid, remove dead copper, pour order 114): 5025.92,887 5025.92,501 4999.92,475 4939.92,415 4939.92,236 4939.92,-23 4948.92,-32 5244.92,-32 5249.92,-27 5249.92,876 5238.92,887
VOUT_R5 on Top Layer "Top Layer-No Net" (solid, remove dead copper, pour order 115): 5770,887 5770,501 5744,475 5684,415 5684,236 5684,-23 5693,-32 5989,-32 5994,-27 5994,876 5983,887
VIN5 on Top Layer "Top Layer-No Net" (solid, remove dead copper, pour order 101): 5731,961 5731,1029 5718,1042 5663,1097 5663,1120 5663,1288 5668,1293 5772,1293 5774,1291 5779,1286 5779,1081 5779,1027 5772,1020 5771,1019 5761,1019 5750,1019 5743,1012 5743,961
VOUT_R6 on Top Layer "Top Layer-No Net" (solid, remove dead copper, pour order 93): 5620,2490 5617,2493 5617,2600 5617,3087 5651,3121 5692,3162 5692,3396 5692,3731 5694,3733 6320,3733 6352,3701 6352,3207 6229,3084 6143,3084 6079,3020 6079,2743 6088,2734 6124,2698 6124,2582 6124,2452 6130,2446 6135,2441 6135,2425 6135,2358 6134,2357 6038,2357 6005,2390 5905,2490 5757,2490
NetU13_8 on Top Layer "Top Layer-No Net" (solid, remove dead copper, pour order 80): 3825,2413 3825,2482 3847,2504 3866,2504 3919,2557 3924,2562 3924,2643 4065,2643 4070,2638 4070,2486 4069,2485 3911,2485 3904,2478 3904,2421 3896,2413
NetU2_8 on Top Layer "Top Layer-No Net" (solid, remove dead copper, pour order 81): 2550,2413 2550,2482 2572,2504 2591,2504 2644,2557 2649,2562 2649,2643 2790,2643 2795,2638 2795,2486 2794,2485 2636,2485 2629,2478 2629,2421 2621,2413
VOUT_R3 on Top Layer "Top Layer-No Net" (solid, remove dead copper, pour order 92): 4384,2358 4384,2926 4377,2933 4273,2933 4259,2919 4191,2851 4191,2797 4191,2789 4237,2743 4256,2724 4256,2489 4256,2385 4283,2358
VOUT_R3 on Top Layer "Top Layer-No Net" (solid, remove dead copper, pour order 91): 3676,3024 3837,2863 3941,2863 3961,2863 4041,2783 4048,2776 4372,2776 4377,2781 4377,2869 4377,2933 4343,2967 4294,3016 3906,3016 3885,3016 3868,3033 3828,3073 3716,3073 3699,3073 3675,3049
VOUT_R1 on Top Layer "Top Layer-No Net" (solid, remove dead copper, pour order 87): 2094,2561 1760,2895 1760,2927 2143,2927 2170,2900 2165,2895 2165,2566
VOUT_R1 on Top Layer "Top Layer-No Net" (solid, remove dead copper, pour order 85): 1120,2561 941,2561 894,2608 894,3723 908,3737 1402,3737 1491,3648 1211,3368 1211,2878 1211,2631 1141,2561
VOUT_R3 on Top Layer "Top Layer-No Net" (solid, remove dead copper, pour order 84): 3369,2561 3276,2561 3258,2579 3258,3721 3265,3728 3516,3728 3552,3692 3544,3684 3544,3477 3544,3106 3465,3027 3465,2657 3369,2561
VOUT_R3 on Top Layer "Top Layer-No Net" (solid, remove dead copper, pour order 83): 3344,2876 3344,3824 3360,3840 3729,3840 3868,3701 3868,3469 3868,3033 3851,3016 3546,3016 3521,2991 3500,2970 3500,2876
VOUT_R3 on Top Layer "Top Layer-No Net" (solid, remove dead copper, pour order 75): 3793,2561 3369,2561 3344,2586 3344,2877 3346,2879 3497,2879 3498,2878 3500,2876 3500,2818 3500,2667 3507,2660 3521,2646 3670,2646 3791,2646 3793,2644
NetU3_8 on Top Layer "Top Layer-No Net" (solid, remove dead copper, pour order 82): 1576,2413 1576,2482 1598,2504 1617,2504 1670,2557 1675,2562 1675,2643 1816,2643 1821,2638 1821,2486 1820,2485 1662,2485 1655,2478 1655,2421 1647,2413
VOUT_R1 on Top Layer "Top Layer-No Net" (solid, remove dead copper, pour order 79): 1095,2876 1095,3749 1139,3793 1874,3793 1950,3717 1950,3172 2008,3114 2206,3114 2214,3106 2225,3095 2225,2876
VOUT_R1 on Top Layer "Top Layer-No Net" (solid, remove dead copper, pour order 76): 2518,2561 2094,2561 2069,2586 2069,2877 2071,2879 2222,2879 2223,2878 2225,2876 2225,2818 2225,2667 2232,2660 2246,2646 2395,2646 2516,2646 2518,2644
VOUT_R1 on Top Layer "Top Layer-No Net" (solid, remove dead copper, pour order 77): 1544,2561 1120,2561 1095,2586 1095,2877 1097,2879 1248,2879 1249,2878 1251,2876 1251,2818 1251,2667 1258,2660 1272,2646 1421,2646 1542,2646 1544,2644
VIN6 on Top Layer "Top Layer-No Net" (solid, remove dead copper, pour order 71): 5573,2377 5573,2088 5539,2054 5523,2038 5523,2030 5523,1914 5524,1913 5526,1911 5742,1911 6040,1911 6169,2040 6174,2045 6174,2237 6174,2282 6171,2285 6164,2285 6162,2283 6162,2232 6157,2227 6156,2226 6141,2226 6129,2226 6122,2219 6120,2217 6120,2199 6120,2138 6106,2124 6100,2118 6053,2118 5724,2118 5667,2175 5646,2196 5646,2208 5624,2230 5624,2251 5624,2376 5623,2377
VIN3 on Top Layer "Top Layer-No Net" (solid, remove dead copper, pour order 70): 4427,2128 4427,2029.24 4323,1927.56 4303,1908 4113,1908 3963,1908 3935,1935.38 3935,2032.18 3942,2039.02 4033,2128 4067,2128
VIN3 on Top Layer "Top Layer-No Net" (solid, remove dead copper, pour order 69): 4427,2284 4427,2126 4424,2123 4377,2123 4374,2126 4374,2213 4378,2217 4385,2224 4391,2224 4408,2224 4413,2229 4415,2231 4415,2248 4415,2284
VIN3 on Top Layer "Top Layer-No Net" (solid, remove dead copper, pour order 66): 3862,2395 3862,1975 3875,1962 4113,1962 4113,2061 4028,2146 4008,2166 3978,2166 3976,2166 3965,2177 3916,2226 3916,2276 3916,2393 3914,2395
VIN1 on Top Layer "Top Layer-No Net" (solid, remove dead copper, pour order 67): 2587,2395 2587,1975 2600,1962 2838,1962 2838,2061 2753,2146 2733,2166 2703,2166 2701,2166 2690,2177 2641,2226 2641,2276 2641,2393 2639,2395
VIN1 on Top Layer "Top Layer-No Net" (solid, remove dead copper, pour order 68): 1613,2395 1613,1975 1626,1962 1864,1962 1864,2061 1779,2146 1759,2166 1729,2166 1727,2166 1716,2177 1667,2226 1667,2276 1667,2393 1665,2395
GND on Bottom Layer "Top Layer-No Net" (solid, remove dead copper, pour order 125): -43,3804 -43,18 41,-66 6709,-66 6803,28 6803,3647 6688,3762
VINAUX on Bottom Layer "Top Layer-No Net" (solid, remove dead copper, pour order 124): 594,2296 594,2209 577,2192 573,2188 561,2188 521,2188 519,2186 519,2090 525,2084 636,2084 639,2087 639,2225 630,2234 624,2240 618,2240 604,2254 604,2255 604,2295 603,2296
VIN on Bottom Layer "Top Layer-No Net" (solid, remove dead copper, pour order 122): 550,1313 6066,1313 6101,1348 6101,1867 6079,1889 6073,1895 5945,1895 1506,1895 1411,1990 1263,2138 -25,2138 -25,1332 -6,1313
AUX_3V3 on Bottom Layer "Top Layer-No Net" (solid, remove dead copper, pour order 120): 542,2798 542,2756 533,2747 533,2720 533,2632 536,2629 621,2629 632,2618 706,2544 721,2544 721,2597 742,2618 742,2639 611,2770 583,2798 544,2798
VIN6 on Bottom Layer "Top Layer-No Net" (solid, remove dead copper, pour order 117): 5573,2377 5573,2047 5615,2005 6130,2005 6194,2069 6230,2105 6230,2151 6196,2151 6195,2152 6127,2152 6111,2136 6097,2122 5725,2122 5624,2223 5624,2255 5624,2376 5623,2377
VIN3 on Bottom Layer "Top Layer-No Net" (solid, remove dead copper, pour order 116): 3863,2395 3863,1925 3880,1908 4305,1908 4425,2028 4476,2079 4476,2144 4476,2149 4474,2151 4436,2151 4428,2159 4423,2164 4423,2221 4382,2221 4378,2217 4374,2213 4374,2151 4374,2144 4358,2128 4016,2128 3956,2188 3918,2226 3918,2395
VOUT_R8 on Bottom Layer "Top Layer-No Net" (solid, remove dead copper, pour order 102): 1305.5,887 1305.5,501 1279.5,475 1219.5,415 1219.5,236 1219.5,-23 1228.5,-32 1524.5,-32 1529.5,-27 1529.5,876 1518.5,887
VOUT_R4 on Bottom Layer "Top Layer-No Net" (solid, remove dead copper, pour order 103): 2049.58,887 2049.58,501 2023.58,475 1963.58,415 1963.58,236 1963.58,-23 1972.58,-32 2268.58,-32 2273.58,-27 2273.58,876 2262.58,887
VOUT_R9 on Bottom Layer "Top Layer-No Net" (solid, remove dead copper, pour order 104): 2793.67,887 2793.67,501 2767.67,475 2707.67,415 2707.67,236 2707.67,-23 2716.67,-32 3012.67,-32 3017.67,-27 3017.67,876 3006.67,887
VOUT_R10 on Bottom Layer "Top Layer-No Net" (solid, remove dead copper, pour order 105): 3537.75,887 3537.75,501 3511.75,475 3451.75,415 3451.75,236 3451.75,-23 3460.75,-32 3756.75,-32 3761.75,-27 3761.75,876 3750.75,887
VOUT_R2 on Bottom Layer "Top Layer-No Net" (solid, remove dead copper, pour order 106): 4281.83,887 4281.83,501 4255.83,475 4195.83,415 4195.83,236 4195.83,-23 4204.83,-32 4500.83,-32 4505.83,-27 4505.83,876 4494.83,887
VOUT_R7 on Bottom Layer "Top Layer-No Net" (solid, remove dead copper, pour order 107): 5025.92,887 5025.92,501 4999.92,475 4939.92,415 4939.92,236 4939.92,-23 4948.92,-32 5244.92,-32 5249.92,-27 5249.92,876 5238.92,887
VOUT_R5 on Bottom Layer "Top Layer-No Net" (solid, remove dead copper, pour order 108): 5770,887 5770,501 5744,475 5684,415 5684,236 5684,-23 5693,-32 5989,-32 5994,-27 5994,876 5983,887
VOUT_R6 on Bottom Layer "Top Layer-No Net" (solid, remove dead copper, pour order 94): 5614,2501 5614,3062 5660,3108 5688,3136 5688,3161 5688,3694 5698,3704 6348,3704 6354,3698 6354,3215 6243,3104 6221,3082 6150,3082 6142,3082 6081,3021 6081,2744 6129,2696 6129,2472 6119,2462 5947,2462 5908,2501
VOUT_R3 on Bottom Layer "Top Layer-No Net" (solid, remove dead copper, pour order 90): 3676,3024 3837,2863 3941,2863 3961,2863 4041,2783 4048,2776 4372,2776 4377,2781 4377,2869 4377,2933 4343,2967 4294,3016 3906,3016 3885,3016 3868,3033 3828,3073 3716,3073 3699,3073 3675,3049
VOUT_R3 on Bottom Layer "Top Layer-No Net" (solid, remove dead copper, pour order 89): 3369,2561 3282,2561 3253,2590 3253,3711 3861,3711 3866,3706 3866,3028 3855,3017 3544,3017 3521,2994 3500,2973 3500,2876 3500,2567 3494,2561
VOUT_R1 on Bottom Layer "Top Layer-No Net" (solid, remove dead copper, pour order 88): 2094,2561 1760,2895 1760,2921 1934,2921 1968,2887 2125,2730 2142,2730 2142,2596 2107,2561
VOUT_R1 on Bottom Layer "Top Layer-No Net" (solid, remove dead copper, pour order 86): 1120,2561 944,2561 892,2613 892,3694 912,3714 1413,3714 1448,3679 1322,3553 1322,3096 1183,2957 1183,2873 1183,2582 1163,2562
VOUT_R3 on Bottom Layer "Top Layer-No Net" (solid, remove dead copper, pour order 72): 3793,2561 3369,2561 3344,2586 3344,2877 3346,2879 3497,2879 3498,2878 3500,2876 3500,2818 3500,2667 3507,2660 3521,2646 3670,2646 3791,2646 3793,2644
VOUT_R1 on Bottom Layer "Top Layer-No Net" (solid, remove dead copper, pour order 78): 1095,2876 1095,3749 1139,3793 1874,3793 1950,3717 1950,3172 2008,3114 2206,3114 2214,3106 2225,3095 2225,2876
VOUT_R1 on Bottom Layer "Top Layer-No Net" (solid, remove dead copper, pour order 73): 2518,2561 2094,2561 2069,2586 2069,2877 2071,2879 2222,2879 2223,2878 2225,2876 2225,2818 2225,2667 2232,2660 2246,2646 2395,2646 2516,2646 2518,2644
VOUT_R1 on Bottom Layer "Top Layer-No Net" (solid, remove dead copper, pour order 74): 1544,2561 1120,2561 1095,2586 1095,2877 1097,2879 1248,2879 1249,2878 1251,2876 1251,2818 1251,2667 1258,2660 1272,2646 1421,2646 1542,2646 1544,2644
VIN1 on Bottom Layer "Top Layer-No Net" (solid, remove dead copper, pour order 64): 2587,2395 2587,1975 2600,1962 2838,1962 2838,2061 2753,2146 2733,2166 2703,2166 2701,2166 2690,2177 2641,2226 2641,2276 2641,2393 2639,2395
VIN1 on Bottom Layer "Top Layer-No Net" (solid, remove dead copper, pour order 65): 1613,2395 1613,1975 1626,1962 1864,1962 1864,2061 1779,2146 1759,2166 1729,2166 1727,2166 1716,2177 1667,2226 1667,2276 1667,2393 1665,2395
GND on Mid-Layer 4 "Top Layer-No Net" (solid, remove dead copper, pour order 69): -24,3765 -24,27 40,-37 6682,-37 6722,3 6722,3669 6658,3733
AUX_3V3 on Mid-Layer 4 "Top Layer-No Net" (solid, remove dead copper, pour order 119): 741,2946 773,2914 773,2861 773,2500 759,2486 758,2485 718,2485 695,2485 693,2487 693,2948 671,2970
AUX_3V3 on Mid-Layer 4 "Top Layer-No Net" (solid, remove dead copper, pour order 118): 693,2487 693,2853 652,2894 599,2947 599,3054 599,3445 607,3453 661,3453 664,3450 671,3443 671,3074 671,3016 705,2982 741,2946 741,2593 741,2491 737,2487
GND on Mid-Layer 1 "Top Layer-No Net" (solid, remove dead copper, pour order 121): -19,3728 -19,-34 18,-71 6698,-71 6775,6 6775,3716 6693,3798
GND on Mid-Layer 2 "Top Layer-No Net" (solid, remove dead copper, pour order 65): -64,3781 -64,35 56,-85 6819,-85 6875,-29 6875,3620 6690,3805
GND on Mid-Layer 3 "Top Layer-No Net" (solid, remove dead copper, pour order 67): -88,3821 -88,-5 -8,-85 6682,-85 6810,43 6810,3773 6754,3829

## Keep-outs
Keep-Out Layer:
  lines w10: 0,0 6700,0 6700,3708.9 0,3708.9 0,0

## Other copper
Top Layer:
  rectangle net NetU11_8: 5522,2388 5613,2566
  region net VOUT_R1: 2094,2681 2195.82,2782.82 1992.9,2985.75 1891.08,2883.92
  rectangle net VIN3: 3862,1908 4113,2061
  rectangle net VIN1: 1613,1907 2841,2061
  pour cut-out: 2747,2177.5 2747,2162 2740,2162 2740,2178
  pour cut-out: 3995.64,2424.91 3995.64,2314.99 4001.86,2314.99 4001.86,2425 4002,2425
  pour cut-out: 2720.64,2424.91 2720.64,2314.99 2726.86,2314.99 2726.86,2425 2727,2425
  pour cut-out: 1746.64,2424.91 1746.64,2314.99 1752.86,2314.99 1752.86,2425 1753,2425
  pour cut-out: 1305,894.83 1305,951.83 1259,951.83 1259,894.83
  pour cut-out: 2049.08,894.83 2049.08,951.83 2003.08,951.83 2003.08,894.83
  pour cut-out: 2793.17,894.83 2793.17,951.83 2747.17,951.83 2747.17,894.83
  pour cut-out: 3537.25,894.83 3537.25,951.83 3491.25,951.83 3491.25,894.83
  pour cut-out: 4281.33,894.83 4281.33,951.83 4235.33,951.83 4235.33,894.83
  pour cut-out: 5025.42,894.83 5025.42,951.83 4979.42,951.83 4979.42,894.83
  pour cut-out: 5769.5,894.83 5769.5,951.83 5723.5,951.83 5723.5,894.83
  pour cut-out: 4388,2348 4388,2291 4434,2291 4434,2348
  pour cut-out: 6135,2348 6135,2291 6181,2291 6181,2348
  pour cut-out: 1335.25,-1815.75 1335.51,-1816 1373.16,-1816 1358.16,-1801 1350,-1801
Bottom Layer:
  rectangle net NetU11_8: 5521,2387 5616,2456
  rectangle net AUX_3V3: 632,2372 742,2618
  rectangle net VOUT_R3: 4251,2467 4377,2933
  region net VOUT_R1: 2191,2780 1977.35,2993.65 1878.35,2894.65 2092,2681
  rectangle net VIN1: 1613,1908 2838,2067
  pour cut-out: 5498,3196 5498,3065 5627,3065 5627,3196
  pour cut-out: 1305.75,2289.25 1314.25,2289.25 1314.25,2310.25 1318,2314 1317,2315 1303,2315
  pour cut-out: 1313.25,2462.25 1313.25,2453.75 1314.5,2455 1334,2455 1334,2462 1335,2463
  pour cut-out: 1507.75,2373.25 1456.25,2373.25 1456.25,2364.75 1507.75,2364.75
  pour cut-out: 3823.25,3340 3932.75,3340 3932.75,3225.74 3823.25,3225.74
  pour cut-out: 1950,3161 1950,3172 1956.38,3165.62 1954.47,3163.71 1954.47,3161
  pour cut-out: 1921.25,3161 2030.75,3161 2030.75,3046.74 1921.25,3046.74

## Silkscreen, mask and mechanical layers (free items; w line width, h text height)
Top Overlay:
  drawing of 161 lines, arcs and shapes, not listed
  text "SEQ 2" at 4596,3557 h80
  text "SEQ 1" at 1832,3095 h80
  text "ON" at 360,2627 h40
  text "ON" at 37,2623 h40
  text "OFF" at 356,2418 h40
  text "OFF" at 5,2411 h40
  text "Monolithic Power Systems" at 2087.56,1813 h60
  text "Xilinx Reference Design Board" at 2087.56,1723 h60
  text "EVREF0101-" at 2089,1558 h60
  text "www.monolithicpower.com" at 2077,1423 h40
  text "SEQ 3" at 4406,392 h80
  text "SEQ 2" at 5491,384 h80
  text "SEQ 4" at 2162,381 h80
Mechanical 1:
  lines w10: 0,0 0,3708.9 6700,3708.9 6700,0 0,0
